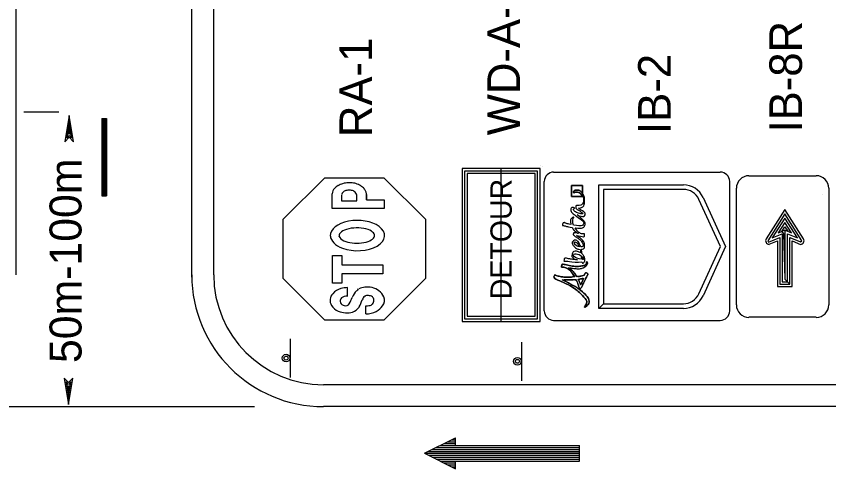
# Model space of a CAD drawing. Extents: x 1482 to 1692, y 225 to 494.
# Drawn here: x 1542.29 to 1587.08, y 383.69 to 408.64 of the extents above; entities that cross this region are included whole.
import ezdxf

# ---------------------------------------------------------------- set-up
doc = ezdxf.new("R2010")
doc.units = 0
for name, color, linetype in [('Level 1', 7, 'Continuous'), ('Level 17', 7, 'Continuous'), ('Level 2', 7, 'Continuous'), ('Level 53', 7, 'Continuous')]:
    doc.layers.add(name, color=color, linetype=linetype)

msp = doc.modelspace()

# ---------------------------------------------------------------- linework, layer by layer
at = {"layer": 'Level 1'}
for points in [[(1545.201, 403.173), (1544.959, 401.721), (1545.201, 401.963), (1545.443, 401.721), (1545.201, 403.173), (1545.201, 402.727), (1545.07, 401.938), (1545.201, 402.069), (1545.332, 401.938), (1545.201, 402.727), (1545.201, 402.277), (1545.177, 402.142), (1545.201, 402.166), (1545.225, 402.142), (1545.201, 402.277), (1545.201, 402.166)], [(1545.171, 387.237), (1545.413, 388.689), (1545.171, 388.447), (1544.929, 388.689), (1545.171, 387.237), (1545.171, 387.683), (1545.302, 388.472), (1545.171, 388.341), (1545.04, 388.472), (1545.171, 387.683), (1545.171, 388.133), (1545.195, 388.268), (1545.171, 388.244), (1545.147, 388.268), (1545.171, 388.133), (1545.171, 388.244)]]:
    msp.add_lwpolyline(points, dxfattribs=at)
at = {"layer": 'Level 17'}
for p, q in [((1571.178, 400.42), (1571.178, 400.42)), ((1571.178, 400.42), (1571.178, 400.42)), ((1571.178, 400.42), (1571.178, 400.42)), ((1571.178, 400.42), (1571.178, 400.42)), ((1569.018, 391.81), (1569.018, 400.247)), ((1571.325, 400.337), (1571.325, 400.337)), ((1571.325, 400.337), (1571.325, 400.337)), ((1571.325, 400.337), (1571.325, 400.337)), ((1571.325, 400.337), (1571.325, 400.337)), ((1582.681, 399.839), (1586.379, 399.839)), ((1581.995, 392.724), (1581.995, 399.161)), ((1587.076, 399.161), (1587.076, 392.724)), ((1559.705, 398.047), (1559.705, 398.851)), ((1560.221, 398.779), (1560.221, 398.467)), ((1560.221, 398.779), (1560.221, 398.467)), ((1561.056, 398.467), (1561.056, 398.773)), ((1561.056, 398.467), (1561.056, 398.773)), ((1561.592, 398.811), (1561.6, 398.524)), ((1561.6, 398.524), (1561.6, 398.824)), ((1586.728, 398.828), (1586.728, 398.828)), ((1560.221, 398.467), (1561.056, 398.467)), ((1560.221, 398.467), (1561.056, 398.467)), ((1561.6, 398.524), (1562.579, 398.524)), ((1562.579, 398.524), (1562.579, 398.047)), ((1562.579, 398.047), (1559.705, 398.047)), ((1584.661, 397.978), (1583.631, 396.365)), ((1585.685, 396.365), (1584.661, 397.978)), ((1559.604, 396.52), (1559.603, 396.535)), ((1560.094, 396.501), (1560.089, 396.52)), ((1583.797, 396.064), (1584.257, 396.256)), ((1584.257, 396.256), (1584.257, 393.74)), ((1585.057, 396.256), (1585.519, 396.058)), ((1585.057, 393.74), (1585.057, 396.25)), ((1559.732, 393.913), (1559.732, 395.443)), ((1559.732, 395.443), (1560.246, 395.443)), ((1560.246, 395.443), (1560.246, 394.939)), ((1560.246, 394.939), (1562.495, 394.939)), ((1562.495, 394.939), (1562.495, 394.441)), ((1562.495, 394.441), (1560.234, 394.441)), ((1560.234, 394.441), (1560.234, 393.913)), ((1560.234, 393.913), (1559.732, 393.913)), ((1584.257, 393.74), (1585.057, 393.74)), ((1560.534, 393.679), (1560.534, 393.187)), ((1561.566, 392.223), (1561.566, 392.673)), ((1562.135, 392.365), (1562.134, 392.362)), ((1586.379, 392.04), (1582.681, 392.04)), ((1557.403, 388.721), (1557.403, 390.854)), ((1570.156, 388.543), (1570.156, 390.676))]:
    msp.add_line(p, q, dxfattribs=at)
for points in [[(1566.866, 400.241), (1566.866, 391.816), (1571.172, 391.816), (1571.172, 400.241)], [(1567.005, 400.1), (1567.005, 391.955), (1571.031, 391.955), (1571.031, 400.1)], [(1562.56, 399.736), (1564.853, 397.443), (1564.853, 394.175), (1562.56, 391.882), (1559.292, 391.882), (1557, 394.175), (1557, 397.443), (1559.292, 399.736)], [(1567.146, 399.96), (1567.146, 392.096), (1570.892, 392.096), (1570.892, 399.96)]]:
    msp.add_lwpolyline(points, close=True, dxfattribs=at)
for points in [[(1584.935, 393.875), (1584.935, 396.448), (1585.531, 396.192), (1585.595, 396.262), (1584.661, 397.74), (1583.713, 396.256), (1583.752, 396.185), (1584.385, 396.448), (1584.385, 393.869), (1584.935, 393.875), (1584.802, 393.996), (1584.802, 396.64), (1585.353, 396.416), (1584.661, 397.498), (1583.969, 396.416), (1584.52, 396.64), (1584.52, 393.996), (1584.802, 393.996), (1584.673, 394.132), (1584.673, 396.851), (1585.019, 396.704), (1584.661, 397.26), (1584.297, 396.69), (1584.501, 396.774), (1584.661, 397.03), (1584.821, 396.786), (1584.655, 396.838), (1584.501, 396.774), (1584.591, 396.646), (1584.655, 394.138), (1584.673, 394.132)], [(1584.935, 393.875), (1584.935, 396.448)]]:
    msp.add_lwpolyline(points, dxfattribs=at)
for centre, radius in [((1557.164, 389.791), 0.213), ((1557.164, 389.791), 0.107), ((1569.917, 389.614), 0.213), ((1569.917, 389.614), 0.107)]:
    msp.add_circle(centre, radius, dxfattribs=at)
for centre, radius, start, end in [((1582.68, 399.155), 0.692, 90, 180), ((1586.384, 399.155), 0.692, 0, 90), ((1560.178, 398.808), 0.477, 134.8528, 175.0441), ((1560.388, 398.659), 0.732, 119.2241, 138.5308), ((1560.388, 398.659), 0.732, 119.2241, 138.5308), ((1560.459, 398.649), 0.778, 103.0674, 123.762), ((1560.689, 397.951), 1.512, 93.3903, 105.6597), ((1560.659, 398.246), 1.215, 79.7521, 92.7916), ((1560.659, 398.246), 1.215, 79.7521, 92.7916), ((1560.564, 397.885), 1.588, 68.3153, 78.6699), ((1560.868, 398.639), 0.774, 48.2922, 68.6031), ((1560.868, 398.639), 0.774, 48.2922, 68.6031), ((1561.09, 398.84), 0.478, 25.3838, 52.6188), ((1560.493, 398.731), 0.283, 125.1198, 169.3117), ((1560.493, 398.731), 0.283, 125.1198, 169.3117), ((1560.577, 398.598), 0.44, 98.6031, 124.217), ((1560.577, 398.598), 0.44, 98.6031, 124.217), ((1560.634, 398.583), 0.468, 80.3417, 105.2342), ((1560.634, 398.583), 0.468, 80.3417, 105.2342), ((1560.691, 398.627), 0.418, 56.5086, 87.0313), ((1560.691, 398.627), 0.418, 56.5086, 87.0313), ((1560.739, 398.706), 0.325, 11.9191, 55.7868), ((1560.739, 398.706), 0.325, 11.9191, 55.7868), ((1560.907, 398.698), 0.706, 16.602, 29.8091), ((1561.429, 398.84), 0.166, 349.7909, 23.5419), ((1583.798, 396.261), 0.199, 147.5015, 269.8949), ((1585.52, 396.258), 0.199, 269.8942, 32.4962), ((1561.639, 392.481), 1.223, 95.9097, 111.9865), ((1561.635, 391.97), 1.731, 81.247, 93.9864), ((1560.123, 392.973), 0.532, 136.1369, 211.3987), ((1560.415, 392.751), 0.898, 104.564, 139.0063), ((1560.557, 392.432), 1.243, 90.6952, 107.1452), ((1561.901, 392.693), 1.175, 136.2465, 157.9263), ((1559.752, 395.095), 2.053, 309.479, 313.4261), ((1561.515, 392.376), 1.361, 55.5092, 73.2894), ((1561.837, 392.858), 0.782, 23.1413, 54.9906), ((1560.426, 392.927), 0.277, 137.3017, 199.0119), ((1560.405, 392.948), 0.264, 203.8064, 262.2407), ((1560.475, 392.797), 0.405, 80.4412, 129.3244), ((1559.224, 393.68), 1.68, 327.9816, 340.979), ((1556.215, 394.993), 5.521, 334.4624, 338.8312), ((1561.7, 392.91), 0.348, 124.2083, 164.1552), ((1561.663, 392.92), 0.319, 82.5761, 120.4776), ((1561.701, 392.824), 0.413, 56.253, 88.7323), ((1561.699, 392.959), 0.31, 5.4374, 44.0625), ((1561.672, 392.983), 0.335, 320.6966, 1.4573), ((1562.102, 392.973), 0.489, 322.0536, 22.7397), ((1560.397, 393.172), 0.87, 213.3662, 245.6734), ((1560.502, 393.507), 1.219, 247.7332, 267.1392), ((1560.443, 392.916), 0.242, 254.131, 328.1476), ((1560.567, 393.041), 0.762, 290.4481, 325.1107), ((1561.574, 393.352), 0.685, 269.0172, 283.5172), ((1561.5, 393.724), 1.502, 272.3841, 294.9519), ((1561.703, 393.029), 0.344, 276.8728, 312.7449), ((1561.626, 393.306), 1.07, 298.4154, 323.6553), ((1582.68, 392.725), 0.692, 180, 270), ((1586.384, 392.725), 0.692, 270, 360), ((1560.536, 393.356), 1.071, 264.8171, 285.9183)]:
    msp.add_arc(centre, radius, start, end, dxfattribs=at)
for centre, major_axis, ratio, start_param, end_param in [((1561.1, 396.546), (1.497, -0.01), 0.558644, 0.656861, 3.168126), ((1561.066, 396.546), (0.977, 0.005), 0.432619, 0.881967, 3.190734), ((1561.1, 396.546), (1.497, -0.01), 0.558644, 4.129576, 6.939747), ((1561.066, 396.546), (0.977, 0.005), 0.432619, 3.890436, 7.165085), ((1561.1, 396.546), (1.497, -0.01), 0.558644, 3.185857, 4.129398), ((1561.066, 396.546), (0.977, 0.005), 0.432619, 3.239639, 3.888884)]:
    msp.add_ellipse(centre, major_axis=major_axis, ratio=ratio, start_param=start_param, end_param=end_param, dxfattribs=at)
at = {"layer": 'Level 2'}
for p, q in [((1542.29, 394.372), (1542.29, 469.813)), ((1551.968, 394.256), (1551.968, 469.813)), ((1553.177, 394.372), (1553.177, 469.813)), ((1544.637, 403.354), (1542.71, 403.354)), ((1547.001, 402.999), (1547.001, 398.733)), ((1547.001, 402.999), (1547.257, 402.999)), ((1547.065, 402.999), (1547.065, 398.733)), ((1547.129, 402.999), (1547.129, 398.733)), ((1547.193, 402.999), (1547.193, 398.733)), ((1547.257, 402.999), (1547.257, 398.733)), ((1571.915, 400.047), (1581.102, 400.047)), ((1571.397, 392.387), (1571.397, 399.529)), ((1571.397, 392.387), (1571.397, 399.529)), ((1581.62, 392.387), (1581.62, 399.529)), ((1574.401, 392.529), (1574.401, 399.344)), ((1574.401, 399.344), (1579.069, 399.344)), ((1579.069, 399.089), (1574.657, 399.089)), ((1574.657, 399.089), (1574.657, 392.785)), ((1547.001, 398.733), (1547.257, 398.733)), ((1580.155, 398.645), (1581.387, 395.937)), ((1581.106, 395.937), (1579.922, 398.54)), ((1579.922, 393.334), (1581.106, 395.937)), ((1581.387, 395.937), (1580.155, 393.228)), ((1574.401, 392.529), (1574.657, 392.785)), ((1574.657, 392.785), (1574.401, 392.529)), ((1579.069, 392.529), (1574.401, 392.529)), ((1574.657, 392.785), (1579.069, 392.785)), ((1571.915, 391.869), (1581.102, 391.869)), ((1620.696, 388.323), (1559.225, 388.323)), ((1537.868, 387.114), (1555.432, 387.114)), ((1620.696, 387.114), (1559.225, 387.114)), ((1564.797, 384.541), (1566.504, 385.395)), ((1566.291, 385.288), (1566.504, 385.288)), ((1566.504, 384.968), (1566.504, 385.395)), ((1565.224, 384.755), (1573.331, 384.755)), ((1565.437, 384.861), (1573.331, 384.861)), ((1565.651, 384.968), (1573.331, 384.968)), ((1565.864, 385.075), (1566.504, 385.075)), ((1566.077, 385.181), (1566.504, 385.181)), ((1566.504, 384.968), (1573.331, 384.968)), ((1573.331, 384.115), (1573.331, 384.968)), ((1564.797, 384.541), (1573.331, 384.541)), ((1564.797, 384.541), (1566.504, 383.688)), ((1565.011, 384.648), (1573.331, 384.648)), ((1565.011, 384.435), (1573.331, 384.435)), ((1565.224, 384.328), (1573.331, 384.328)), ((1565.437, 384.221), (1573.331, 384.221)), ((1565.651, 384.115), (1573.331, 384.115)), ((1565.864, 384.008), (1566.504, 384.008)), ((1566.077, 383.901), (1566.504, 383.901)), ((1566.504, 384.115), (1573.331, 384.115)), ((1566.504, 383.688), (1566.504, 384.115)), ((1566.291, 383.795), (1566.504, 383.795))]:
    msp.add_line(p, q, dxfattribs=at)
for centre, radius, start, end in [((1571.915, 399.529), 0.518, 90, 180), ((1581.102, 399.529), 0.518, 360, 90), ((1579.069, 398.152), 1.193, 24.4568, 90), ((1579.069, 398.152), 0.937, 24.4568, 90), ((1559.225, 394.372), 7.258, 180, 270), ((1559.225, 394.372), 6.048, 180, 270), ((1579.069, 393.722), 0.937, 270, 335.5432), ((1579.069, 393.722), 1.193, 270, 335.5432), ((1571.915, 392.387), 0.518, 180, 270), ((1581.102, 392.387), 0.518, 270, 360)]:
    msp.add_arc(centre, radius, start, end, dxfattribs=at)
at = {"layer": 'Level 53'}
msp.add_line((1573.513, 398.867), (1573.513, 398.716), dxfattribs=at)
msp.add_lwpolyline([(1573.513, 398.867), (1573.513, 399.307), (1572.905, 399.307), (1572.905, 398.699), (1573.513, 398.699), (1573.513, 398.716)], dxfattribs=at)
for points, degree in [([(1572.905, 398.699), (1572.905, 398.699), (1573.513, 398.699), (1573.513, 398.699), (1573.513, 398.699), (1573.513, 398.716), (1573.513, 398.716), (1573.434, 398.849), (1573.283, 398.937), (1573.158, 398.937), (1573.051, 398.937), (1573.056, 398.88), (1573.041, 398.887), (1572.998, 398.905), (1573.023, 399.039), (1573.174, 399.047), (1573.303, 399.054), (1573.428, 398.986), (1573.513, 398.867), (1573.513, 398.867), (1573.513, 399.307), (1573.513, 399.307), (1573.513, 399.307), (1572.905, 399.307), (1572.905, 399.307), (1572.905, 399.307), (1572.905, 398.699), (1572.905, 398.699)], 3), ([(1573.513, 398.716), (1573.434, 398.849), (1573.283, 398.937), (1573.158, 398.937), (1573.051, 398.937), (1573.056, 398.88), (1573.041, 398.887), (1572.998, 398.905), (1573.023, 399.039), (1573.174, 399.047), (1573.303, 399.054), (1573.428, 398.986), (1573.513, 398.867)], 3), ([(1573.282, 398.055), (1573.407, 398.07), (1573.623, 398.154), (1573.623, 398.491), (1573.623, 398.642), (1573.58, 398.771), (1573.513, 398.867)], 3), ([(1573.513, 398.716), (1573.546, 398.66), (1573.567, 398.597), (1573.567, 398.529)], 2), ([(1573.567, 398.529), (1573.567, 398.279), (1573.373, 398.215), (1573.277, 398.203), (1573.213, 398.195), (1573.12, 398.208), (1573.133, 398.098), (1573.141, 398.021), (1573.292, 397.951), (1573.418, 397.853), (1573.527, 397.769), (1573.516, 397.732), (1573.423, 397.751), (1573.306, 397.776), (1573.032, 397.873), (1573.012, 397.985), (1573.003, 398.036), (1573.094, 398.055), (1573.037, 398.078), (1572.98, 398.102), (1572.858, 398.08), (1572.858, 397.965), (1572.858, 397.884), (1572.943, 397.787), (1573.041, 397.708), (1573.126, 397.638), (1573.642, 397.288), (1573.53, 397.141), (1573.478, 397.072), (1573.266, 397.078), (1573.017, 397.121)], 3), ([(1573.208, 397.687), (1573.384, 397.609), (1573.61, 397.565), (1573.644, 397.682), (1573.685, 397.82), (1573.456, 397.928), (1573.282, 398.055)], 3), ([(1573.017, 397.121), (1572.949, 397.295), (1572.971, 397.441), (1573.011, 397.523), (1573.03, 397.563), (1573.027, 397.569), (1572.983, 397.551), (1572.917, 397.526), (1572.815, 397.386), (1572.862, 397.166), (1572.863, 397.161), (1572.864, 397.156), (1572.866, 397.151)], 3), ([(1573.094, 396.969), (1573.33, 396.942), (1573.541, 396.951), (1573.608, 397.058), (1573.731, 397.255), (1573.407, 397.534), (1573.208, 397.687)], 3), ([(1572.866, 397.151), (1572.785, 397.168), (1572.702, 397.189), (1572.622, 397.211), (1572.549, 397.232), (1572.422, 397.292), (1572.397, 397.135), (1572.39, 397.085), (1572.414, 397.106), (1572.482, 397.09), (1572.606, 397.059), (1572.768, 397.021), (1572.93, 396.993)], 3), ([(1572.93, 396.993), (1573.005, 396.864), (1573.129, 396.744), (1573.292, 396.656)], 2), ([(1573.172, 396.543), (1573.318, 396.529), (1573.638, 396.434), (1573.622, 396.596), (1573.615, 396.66), (1573.605, 396.632), (1573.55, 396.636), (1573.358, 396.65), (1573.194, 396.811), (1573.094, 396.969)], 3), ([(1573.292, 396.656), (1573.217, 396.671), (1573.134, 396.695), (1573.077, 396.696), (1573.018, 396.698), (1573.005, 396.657), (1573, 396.641), (1572.99, 396.607), (1573.008, 396.565), (1573.066, 396.524), (1573.201, 396.428), (1573.416, 396.306), (1573.506, 396.121), (1573.57, 395.988), (1573.505, 395.93), (1573.405, 395.926)], 3), ([(1573.44, 395.785), (1573.547, 395.798), (1573.629, 395.868), (1573.614, 396.03), (1573.592, 396.261), (1573.309, 396.466), (1573.172, 396.543)], 3), ([(1573.405, 395.926), (1573.397, 395.953), (1573.389, 395.976), (1573.38, 395.996), (1573.274, 396.237), (1573.113, 396.319), (1573.015, 396.258), (1572.922, 396.2), (1572.95, 396.034), (1573.088, 395.903), (1573.156, 395.839), (1573.273, 395.789), (1573.379, 395.783)], 3), ([(1573.1, 396.055), (1573.025, 396.136), (1573.031, 396.176), (1573.051, 396.187), (1573.094, 396.209), (1573.248, 396.114), (1573.332, 395.933)], 3), ([(1573.332, 395.933), (1573.249, 395.948), (1573.159, 395.992), (1573.1, 396.055)], 2), ([(1573.412, 395.592), (1573.228, 395.705), (1572.98, 395.696), (1572.938, 395.53), (1572.89, 395.338), (1573.076, 395.241), (1573.231, 395.2)], 3), ([(1573.447, 395.241), (1573.252, 395.267), (1572.98, 395.369), (1573.024, 395.495), (1573.049, 395.568), (1573.278, 395.53), (1573.43, 395.436)], 3), ([(1573.379, 395.783), (1573.391, 395.728), (1573.402, 395.664), (1573.412, 395.592)], 2), ([(1573.478, 395.543), (1573.468, 395.623), (1573.455, 395.708), (1573.44, 395.785)], 2), ([(1573.464, 395.097), (1573.486, 395.028), (1573.537, 395.001), (1573.592, 395.089), (1573.629, 395.149), (1573.642, 395.283), (1573.575, 395.418), (1573.551, 395.466), (1573.518, 395.508), (1573.478, 395.543)], 3), ([(1573.733, 395.054), (1573.724, 394.989), (1573.635, 394.903), (1573.488, 394.877), (1573.225, 394.83), (1572.965, 394.858), (1572.577, 394.935), (1572.504, 394.95), (1572.377, 395), (1572.353, 394.841), (1572.345, 394.79), (1572.37, 394.817), (1572.437, 394.803), (1572.725, 394.741), (1572.933, 394.505), (1573.073, 394.268), (1572.742, 394.244), (1572.375, 394.254), (1572.15, 394.316), (1571.961, 394.368), (1571.996, 394.431), (1571.956, 394.353), (1571.914, 394.272), (1571.969, 394.184), (1572.111, 394.114), (1572.252, 394.043), (1573.02, 393.717), (1573.538, 393.196), (1573.803, 392.929), (1573.666, 392.688), (1573.626, 392.64), (1573.592, 392.6), (1573.644, 392.586), (1573.696, 392.634), (1573.929, 392.85), (1573.795, 393.165), (1573.681, 393.28), (1573.364, 393.597), (1572.681, 393.965), (1572.392, 394.114), (1572.555, 394.101), (1572.828, 394.096), (1573.149, 394.126), (1573.227, 393.965), (1573.274, 393.82), (1573.291, 393.752), (1573.311, 393.678), (1573.341, 393.633), (1573.375, 393.631), (1573.413, 393.63), (1573.444, 393.679), (1573.478, 393.751), (1573.539, 393.879), (1573.716, 394.253), (1573.769, 394.345), (1573.815, 394.424), (1573.779, 394.462), (1573.73, 394.486), (1573.665, 394.516), (1573.628, 394.433), (1573.604, 394.351), (1573.495, 394.32), (1573.349, 394.295), (1573.189, 394.279), (1573.072, 394.469), (1572.916, 394.656), (1572.721, 394.764), (1572.884, 394.737), (1573.437, 394.667), (1573.671, 394.842), (1573.723, 394.88), (1573.779, 394.965), (1573.771, 395.048), (1573.767, 395.087), (1573.741, 395.107), (1573.733, 395.103), (1573.725, 395.099), (1573.737, 395.077), (1573.733, 395.054)], 3), ([(1573.733, 395.054), (1573.724, 394.989), (1573.635, 394.903), (1573.488, 394.877), (1573.225, 394.83), (1572.965, 394.858), (1572.577, 394.935), (1572.504, 394.95), (1572.377, 395), (1572.353, 394.841), (1572.345, 394.79), (1572.37, 394.817), (1572.437, 394.803), (1572.725, 394.741), (1572.933, 394.505), (1573.073, 394.268)], 3), ([(1573.231, 395.2), (1573.076, 395.213), (1572.887, 395.238), (1572.712, 395.273), (1572.639, 395.287), (1572.512, 395.337), (1572.487, 395.178), (1572.48, 395.128), (1572.503, 395.136), (1572.572, 395.14), (1572.663, 395.145), (1573.219, 395.044), (1573.464, 395.097)], 3), ([(1572.721, 394.764), (1572.884, 394.737), (1573.437, 394.667), (1573.671, 394.842), (1573.723, 394.88), (1573.779, 394.965), (1573.771, 395.048), (1573.767, 395.087), (1573.741, 395.107), (1573.733, 395.103), (1573.725, 395.099), (1573.737, 395.077), (1573.733, 395.054)], 3), ([(1573.43, 395.436), (1573.436, 395.375), (1573.442, 395.31), (1573.447, 395.241)], 2), ([(1573.507, 395.236), (1573.506, 395.27), (1573.502, 395.324), (1573.496, 395.387)], 2), ([(1573.496, 395.387), (1573.532, 395.354), (1573.558, 395.316), (1573.564, 395.276)], 2), ([(1573.565, 395.221), (1573.557, 395.229), (1573.546, 395.235), (1573.533, 395.235), (1573.525, 395.235), (1573.516, 395.235), (1573.507, 395.236)], 3), ([(1573.564, 395.276), (1573.568, 395.254), (1573.567, 395.235), (1573.565, 395.221)], 2), ([(1573.189, 394.279), (1573.072, 394.469), (1572.916, 394.656), (1572.721, 394.764)], 2), ([(1573.073, 394.268), (1572.742, 394.244), (1572.375, 394.254), (1572.15, 394.316), (1571.961, 394.368), (1571.996, 394.431), (1571.956, 394.353), (1571.914, 394.272), (1571.969, 394.184), (1572.111, 394.114), (1572.252, 394.043), (1573.02, 393.717), (1573.538, 393.196), (1573.803, 392.929), (1573.666, 392.688), (1573.626, 392.64), (1573.592, 392.6), (1573.644, 392.586), (1573.696, 392.634), (1573.929, 392.85), (1573.795, 393.165), (1573.681, 393.28), (1573.364, 393.597), (1572.681, 393.965), (1572.392, 394.114)], 3), ([(1573.149, 394.126), (1573.227, 393.965), (1573.274, 393.82), (1573.291, 393.752), (1573.311, 393.678), (1573.341, 393.633), (1573.375, 393.631), (1573.413, 393.63), (1573.444, 393.679), (1573.478, 393.751), (1573.539, 393.879), (1573.716, 394.253), (1573.769, 394.345), (1573.815, 394.424), (1573.779, 394.462), (1573.73, 394.486), (1573.665, 394.516), (1573.628, 394.433), (1573.604, 394.351)], 3), ([(1573.604, 394.351), (1573.495, 394.32), (1573.349, 394.295), (1573.189, 394.279)], 2), ([(1573.268, 394.139), (1573.397, 394.154), (1573.49, 394.171), (1573.559, 394.189)], 2), ([(1573.403, 393.835), (1573.372, 393.919), (1573.327, 394.026), (1573.268, 394.139), (1573.397, 394.154), (1573.49, 394.171), (1573.559, 394.189), (1573.529, 394.107), (1573.481, 393.989), (1573.403, 393.835)], 3), ([(1573.559, 394.189), (1573.529, 394.107), (1573.481, 393.989), (1573.403, 393.835)], 2), ([(1572.392, 394.114), (1572.555, 394.101), (1572.828, 394.096), (1573.149, 394.126)], 2), ([(1573.403, 393.835), (1573.372, 393.919), (1573.327, 394.026), (1573.268, 394.139)], 2)]:
    msp.add_open_spline(points, degree=degree, dxfattribs=at)

# ---------------------------------------------------------------- texts
at = {"layer": 'Level 17'}
for s, height, p in [('WD-A-44', 1.8, (1570.06, 402.073)), ('IB-8R', 1.8, (1585.605, 402.228)), ('RA-1', 1.8, (1561.909, 401.975)), ('IB-2', 1.8, (1578.37, 402.148)), ('50m-100m', 1.764, (1545.888, 389.517)), ('DETOUR', 1.1758, (1569.606, 393.035))]:
    msp.add_text(s, height=height, rotation=90, dxfattribs=at).set_placement(p)

doc.saveas('drawing.dxf')
